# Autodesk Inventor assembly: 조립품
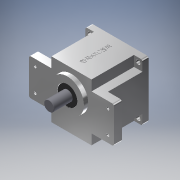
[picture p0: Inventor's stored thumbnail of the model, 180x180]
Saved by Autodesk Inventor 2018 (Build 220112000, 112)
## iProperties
Created: 2020-07
Part Number: 조립품
Material: 일반
Document SubType Name: Assembly
Designer: Admin
Author: Admin
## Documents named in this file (10)
- C:\Users\Admin\Desktop\700707V1008\조립품.iam
- C:\Users\Admin\Desktop\700707V1008\본체.ipt
- C:\Users\Admin\Desktop\700707V1008\서브 축.ipt
- C:\Users\Admin\Desktop\700707V1008\메인 축.ipt
- C:\Users\Admin\Desktop\700707V1008\베어링 608.ipt
- C:\Users\Admin\Desktop\700707V1008\베어링 6003.ipt
- C:\Users\Admin\Desktop\700707V1008\오일 실 17 32 8.ipt
- C:\Users\Admin\Desktop\700707V1008\커버.ipt
- C:\Users\Admin\Desktop\700707V1008\볼트 M4.ipt
- C:\Users\Admin\Desktop\700707V1008\오일 실 8 22 7.ipt
